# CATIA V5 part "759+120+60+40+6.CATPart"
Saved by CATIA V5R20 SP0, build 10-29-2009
Part number: 759+120+60+40+6
Revision: TUTTO
Definition: NON CONOSCIUTO
Nomenclature: 759+120+60+40+6
Source: Unknown
Bounding box of the stored display mesh (mm): x -60 to 60, y -30 to 30, z 0 to 40
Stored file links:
  C:\Users\Utente\Desktop\IO LAVORO\3D X SITO CF\X 3D SITO CF 27-09-2020\759\759+120+60+40+6.CATPart
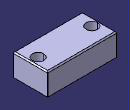
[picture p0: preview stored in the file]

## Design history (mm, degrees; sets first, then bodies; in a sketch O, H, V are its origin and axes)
Body1 "Smusso4" (main body)
  Solid1: solid without history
